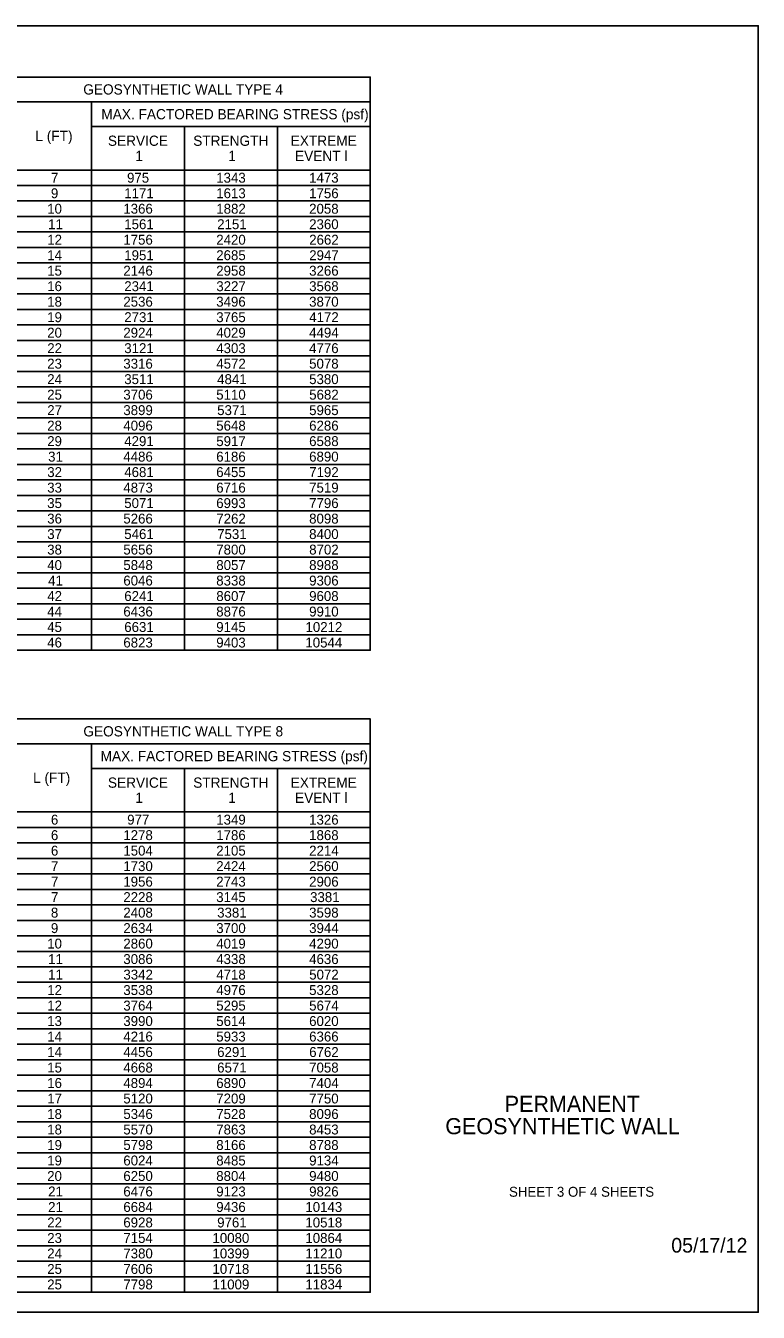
# Model space of a CAD drawing. Extents: x 99862 to 103151, y 100000 to 111076.
# Drawn here: x 101968 to 103151, y 106000 to 108076 of the extents above; entities that cross this region are included whole.
import ezdxf

# ---------------------------------------------------------------- set-up
doc = ezdxf.new("R2010")
doc.units = 0
for name, color, linetype in [('Level 1', 7, 'Continuous'), ('Level 20', 7, 'Continuous'), ('Level 40', 7, 'Continuous'), ('Level 60', 7, 'Continuous'), ('Level 62', 7, 'Continuous')]:
    doc.layers.add(name, color=color, linetype=linetype)

msp = doc.modelspace()

# ---------------------------------------------------------------- linework, layer by layer
at = {"layer": 'Level 1'}
msp.add_lwpolyline([(99862, 105999.5), (103151, 105999.5), (103151, 108075.5), (99862, 108075.5)], close=True, dxfattribs=at)
at = {"layer": 'Level 40'}
for p, q in [((100094.6, 107952.7), (102524.6, 107952.7)), ((102074.6, 107952.7), (102074.6, 107067.7)), ((102074.6, 107912.7), (102524.6, 107912.7)), ((102224.6, 107912.7), (102224.6, 107067.7)), ((102374.6, 107912.7), (102374.6, 107067.7)), ((99944.6, 107842.7), (102524.6, 107842.7)), ((99944.6, 107817.7), (102524.6, 107817.7)), ((99944.6, 107792.7), (102524.6, 107792.7)), ((99944.6, 107767.7), (102524.6, 107767.7)), ((99944.6, 107742.7), (102524.6, 107742.7)), ((99944.6, 107717.7), (102524.6, 107717.7)), ((99944.6, 107692.7), (102524.6, 107692.7)), ((99944.6, 107667.7), (102524.6, 107667.7)), ((99944.6, 107642.7), (102524.6, 107642.7)), ((99944.6, 107617.7), (102524.6, 107617.7)), ((99944.6, 107592.7), (102524.6, 107592.7)), ((99944.6, 107567.7), (102524.6, 107567.7)), ((99944.6, 107542.7), (102524.6, 107542.7)), ((99944.6, 107517.7), (102524.6, 107517.7)), ((99944.6, 107492.7), (102524.6, 107492.7)), ((99944.6, 107467.7), (102524.6, 107467.7)), ((99944.6, 107442.7), (102524.6, 107442.7)), ((99944.6, 107417.7), (102524.6, 107417.7)), ((99944.6, 107392.7), (102524.6, 107392.7)), ((99944.6, 107367.7), (102524.6, 107367.7)), ((99944.6, 107342.7), (102524.6, 107342.7)), ((99944.6, 107317.7), (102524.6, 107317.7)), ((99944.6, 107292.7), (102524.6, 107292.7)), ((99944.6, 107267.7), (102524.6, 107267.7)), ((99944.6, 107242.7), (102524.6, 107242.7)), ((99944.6, 107217.7), (102524.6, 107217.7)), ((99944.6, 107192.7), (102524.6, 107192.7)), ((99944.6, 107167.7), (102524.6, 107167.7)), ((99944.6, 107142.7), (102524.6, 107142.7)), ((99944.6, 107117.7), (102524.6, 107117.7)), ((99944.6, 107092.7), (102524.6, 107092.7)), ((100094.6, 106916.9), (102524.6, 106916.9)), ((102074.6, 106916.9), (102074.6, 106031.9)), ((102074.6, 106876.9), (102524.6, 106876.9)), ((102224.6, 106876.9), (102224.6, 106031.9)), ((102374.6, 106876.9), (102374.6, 106031.9)), ((99944.6, 106806.9), (102524.6, 106806.9)), ((99944.6, 106781.9), (102524.6, 106781.9)), ((99944.6, 106756.9), (102524.6, 106756.9)), ((99944.6, 106731.9), (102524.6, 106731.9)), ((99944.6, 106706.9), (102524.6, 106706.9)), ((99944.6, 106681.9), (102524.6, 106681.9)), ((99944.6, 106656.9), (102524.6, 106656.9)), ((99944.6, 106631.9), (102524.6, 106631.9)), ((99944.6, 106606.9), (102524.6, 106606.9)), ((99944.6, 106581.9), (102524.6, 106581.9)), ((99944.6, 106556.9), (102524.6, 106556.9)), ((99944.6, 106531.9), (102524.6, 106531.9)), ((99944.6, 106506.9), (102524.6, 106506.9)), ((99944.6, 106481.9), (102524.6, 106481.9)), ((99944.6, 106456.9), (102524.6, 106456.9)), ((99944.6, 106431.9), (102524.6, 106431.9)), ((99944.6, 106406.9), (102524.6, 106406.9)), ((99944.6, 106381.9), (102524.6, 106381.9)), ((99944.6, 106356.9), (102524.6, 106356.9)), ((99944.6, 106331.9), (102524.6, 106331.9)), ((99944.6, 106306.9), (102524.6, 106306.9)), ((99944.6, 106281.9), (102524.6, 106281.9)), ((99944.6, 106256.9), (102524.6, 106256.9)), ((99944.6, 106231.9), (102524.6, 106231.9)), ((99944.6, 106206.9), (102524.6, 106206.9)), ((99944.6, 106181.9), (102524.6, 106181.9)), ((99944.6, 106156.9), (102524.6, 106156.9)), ((99944.6, 106131.9), (102524.6, 106131.9)), ((99944.6, 106106.9), (102524.6, 106106.9)), ((99944.6, 106081.9), (102524.6, 106081.9)), ((99944.6, 106056.9), (102524.6, 106056.9))]:
    msp.add_line(p, q, dxfattribs=at)
for points in [[(99944.6, 107992.7), (102524.6, 107992.7), (102524.6, 107067.7), (99944.6, 107067.7)], [(99944.6, 106956.9), (102524.6, 106956.9), (102524.6, 106031.9), (99944.6, 106031.9)]]:
    msp.add_lwpolyline(points, close=True, dxfattribs=at)
at = {"layer": 'Level 60'}
msp.add_line((103151, 108075.5), (103151, 108075.5), dxfattribs=at)

# ---------------------------------------------------------------- texts
at = {"layer": 'Level 1'}
msp.add_text('05/17/12', height=23.62, dxfattribs=at).set_placement((103010.5, 106095.8))
at = {"layer": 'Level 20'}
for s, height, p in [('GEOSYNTHETIC WALL TYPE 4', 16.5, (102061.2, 107964.5)), ('MAX. FACTORED BEARING STRESS (psf)', 16.5, (102090.4, 107924.5)), ('L (FT)', 16.5, (101983.9, 107889.5)), ('SERVICE', 16.5, (102101, 107881.7)), ('STRENGTH', 16.5, (102238.7, 107881.7)), ('EXTREME', 16.5, (102396.1, 107881.7)), ('1', 16.5, (102145.2, 107857.2)), ('1', 16.5, (102295.2, 107857.2)), ('EVENT l', 16.5, (102403.1, 107857.2)), ('7', 16, (102009.2, 107822.2)), ('975', 16, (102131.9, 107822.2)), ('1343', 16, (102275.9, 107822.2)), ('1473', 16, (102425.9, 107822.2)), ('9', 16, (102009, 107797.2)), ('1171', 16, (102127.4, 107797.2)), ('1613', 16, (102275.9, 107797.2)), ('1756', 16, (102425.9, 107797.2)), ('10', 16, (102003, 107772.2)), ('1366', 16, (102125.9, 107772.2)), ('1882', 16, (102276, 107772.2)), ('2058', 16, (102425.9, 107772.2)), ('11', 16, (102004.5, 107747.2)), ('1561', 16, (102127.4, 107747.2)), ('2151', 16, (102277.4, 107747.2)), ('2360', 16, (102425.9, 107747.2)), ('12', 16, (102003.1, 107722.2)), ('1756', 16, (102125.9, 107722.2)), ('2420', 16, (102275.9, 107722.2)), ('2662', 16, (102426, 107722.2)), ('14', 16, (102003, 107697.2)), ('1951', 16, (102127.4, 107697.2)), ('2685', 16, (102275.9, 107697.2)), ('2947', 16, (102426, 107697.2)), ('15', 16, (102003, 107672.2)), ('2146', 16, (102125.9, 107672.2)), ('2958', 16, (102275.9, 107672.2)), ('3266', 16, (102425.9, 107672.2)), ('16', 16, (102003, 107647.2)), ('2341', 16, (102127.4, 107647.2)), ('3227', 16, (102276, 107647.2)), ('3568', 16, (102425.9, 107647.2)), ('18', 16, (102003, 107622.2)), ('2536', 16, (102125.9, 107622.2)), ('3496', 16, (102275.9, 107622.2)), ('3870', 16, (102425.9, 107622.2)), ('19', 16, (102003, 107597.2)), ('2731', 16, (102127.4, 107597.2)), ('3765', 16, (102275.9, 107597.2)), ('4172', 16, (102426, 107597.2)), ('20', 16, (102003, 107572.2)), ('2924', 16, (102125.9, 107572.2)), ('4029', 16, (102275.9, 107572.2)), ('4494', 16, (102425.9, 107572.2)), ('22', 16, (102003.1, 107547.2)), ('3121', 16, (102127.4, 107547.2)), ('4303', 16, (102275.9, 107547.2)), ('4776', 16, (102425.9, 107547.2)), ('23', 16, (102003, 107522.2)), ('3316', 16, (102125.9, 107522.2)), ('4572', 16, (102276, 107522.2)), ('5078', 16, (102425.9, 107522.2)), ('24', 16, (102003, 107497.2)), ('3511', 16, (102127.4, 107497.2)), ('4841', 16, (102277.4, 107497.2)), ('5380', 16, (102425.9, 107497.2)), ('25', 16, (102003, 107472.2)), ('3706', 16, (102125.9, 107472.2)), ('5110', 16, (102275.9, 107472.2)), ('5682', 16, (102426, 107472.2)), ('27', 16, (102003.1, 107447.2)), ('3899', 16, (102125.9, 107447.2)), ('5371', 16, (102277.4, 107447.2)), ('5965', 16, (102425.9, 107447.2)), ('28', 16, (102003, 107422.2)), ('4096', 16, (102125.9, 107422.2)), ('5648', 16, (102275.9, 107422.2)), ('6286', 16, (102425.9, 107422.2)), ('29', 16, (102003, 107397.2)), ('4291', 16, (102127.4, 107397.2)), ('5917', 16, (102276, 107397.2)), ('6588', 16, (102425.9, 107397.2)), ('31', 16, (102004.5, 107372.2)), ('4486', 16, (102125.9, 107372.2)), ('6186', 16, (102275.9, 107372.2)), ('6890', 16, (102425.9, 107372.2)), ('32', 16, (102003.1, 107347.2)), ('4681', 16, (102127.4, 107347.2)), ('6455', 16, (102275.9, 107347.2)), ('7192', 16, (102426, 107347.2)), ('33', 16, (102003, 107322.2)), ('4873', 16, (102125.9, 107322.2)), ('6716', 16, (102275.9, 107322.2)), ('7519', 16, (102425.9, 107322.2)), ('35', 16, (102003, 107297.2)), ('5071', 16, (102127.4, 107297.2)), ('6993', 16, (102275.9, 107297.2)), ('7796', 16, (102425.9, 107297.2)), ('36', 16, (102003, 107272.2)), ('5266', 16, (102125.9, 107272.2)), ('7262', 16, (102276, 107272.2)), ('8098', 16, (102425.9, 107272.2)), ('37', 16, (102003.1, 107247.2)), ('5461', 16, (102127.4, 107247.2)), ('7531', 16, (102277.4, 107247.2)), ('8400', 16, (102425.9, 107247.2)), ('38', 16, (102003, 107222.2)), ('5656', 16, (102125.9, 107222.2)), ('7800', 16, (102275.9, 107222.2)), ('8702', 16, (102426, 107222.2)), ('40', 16, (102003, 107197.2)), ('5848', 16, (102125.9, 107197.2)), ('8057', 16, (102276, 107197.2)), ('8988', 16, (102425.9, 107197.2)), ('41', 16, (102004.5, 107172.2)), ('6046', 16, (102125.9, 107172.2)), ('8338', 16, (102275.9, 107172.2)), ('9306', 16, (102425.9, 107172.2)), ('42', 16, (102003.1, 107147.2)), ('6241', 16, (102127.4, 107147.2)), ('8607', 16, (102276, 107147.2)), ('9608', 16, (102425.9, 107147.2)), ('44', 16, (102003, 107122.2)), ('6436', 16, (102125.9, 107122.2)), ('8876', 16, (102275.9, 107122.2)), ('9910', 16, (102425.9, 107122.2)), ('45', 16, (102003, 107097.2)), ('6631', 16, (102127.4, 107097.2)), ('9145', 16, (102275.9, 107097.2)), ('10212', 16, (102420, 107097.2)), ('46', 16, (102003, 107072.2)), ('6823', 16, (102125.9, 107072.2)), ('9403', 16, (102275.9, 107072.2)), ('10544', 16, (102419.8, 107072.2)), ('GEOSYNTHETIC WALL TYPE 8', 16.5, (102061.4, 106928.7)), ('MAX. FACTORED BEARING STRESS (psf)', 16.5, (102089.2, 106888.7)), ('L (FT)', 16.5, (101980.2, 106853.7)), ('SERVICE', 16.5, (102101, 106845.9)), ('STRENGTH', 16.5, (102238.7, 106845.9)), ('EXTREME', 16.5, (102396.1, 106845.9)), ('1', 16.5, (102145.2, 106821.4)), ('1', 16.5, (102295.2, 106821.4)), ('EVENT l', 16.5, (102403.1, 106821.4)), ('6', 16, (102009, 106786.4)), ('977', 16, (102132.1, 106786.4)), ('1349', 16, (102275.9, 106786.4)), ('1326', 16, (102425.9, 106786.4)), ('6', 16, (102009, 106761.4)), ('1278', 16, (102125.9, 106761.4)), ('1786', 16, (102275.9, 106761.4)), ('1868', 16, (102425.9, 106761.4)), ('6', 16, (102009, 106736.4)), ('1504', 16, (102125.9, 106736.4)), ('2105', 16, (102275.9, 106736.4)), ('2214', 16, (102425.9, 106736.4)), ('7', 16, (102009.2, 106711.4)), ('1730', 16, (102125.9, 106711.4)), ('2424', 16, (102275.9, 106711.4)), ('2560', 16, (102425.9, 106711.4)), ('7', 16, (102009.2, 106686.4)), ('1956', 16, (102125.9, 106686.4)), ('2743', 16, (102275.9, 106686.4)), ('2906', 16, (102425.9, 106686.4)), ('7', 16, (102009.2, 106661.4)), ('2228', 16, (102125.9, 106661.4)), ('3145', 16, (102275.9, 106661.4)), ('3381', 16, (102427.4, 106661.4)), ('8', 16, (102009, 106636.4)), ('2408', 16, (102125.9, 106636.4)), ('3381', 16, (102277.4, 106636.4)), ('3598', 16, (102425.9, 106636.4)), ('9', 16, (102009, 106611.4)), ('2634', 16, (102125.9, 106611.4)), ('3700', 16, (102275.9, 106611.4)), ('3944', 16, (102425.9, 106611.4)), ('10', 16, (102003, 106586.4)), ('2860', 16, (102125.9, 106586.4)), ('4019', 16, (102275.9, 106586.4)), ('4290', 16, (102425.9, 106586.4)), ('11', 16, (102004.5, 106561.4)), ('3086', 16, (102125.9, 106561.4)), ('4338', 16, (102275.9, 106561.4)), ('4636', 16, (102425.9, 106561.4)), ('11', 16, (102004.5, 106536.4)), ('3342', 16, (102126, 106536.4)), ('4718', 16, (102275.9, 106536.4)), ('5072', 16, (102426, 106536.4)), ('12', 16, (102003.1, 106511.4)), ('3538', 16, (102125.9, 106511.4)), ('4976', 16, (102275.9, 106511.4)), ('5328', 16, (102425.9, 106511.4)), ('12', 16, (102003.1, 106486.4)), ('3764', 16, (102125.9, 106486.4)), ('5295', 16, (102275.9, 106486.4)), ('5674', 16, (102425.9, 106486.4)), ('13', 16, (102003, 106461.4)), ('3990', 16, (102125.9, 106461.4)), ('5614', 16, (102275.9, 106461.4)), ('6020', 16, (102425.9, 106461.4)), ('14', 16, (102003, 106436.4)), ('4216', 16, (102125.9, 106436.4)), ('5933', 16, (102275.9, 106436.4)), ('6366', 16, (102425.9, 106436.4)), ('14', 16, (102003, 106411.4)), ('4456', 16, (102125.9, 106411.4)), ('6291', 16, (102277.4, 106411.4)), ('6762', 16, (102426, 106411.4)), ('15', 16, (102003, 106386.4)), ('4668', 16, (102125.9, 106386.4)), ('6571', 16, (102277.4, 106386.4)), ('7058', 16, (102425.9, 106386.4)), ('16', 16, (102003, 106361.4)), ('4894', 16, (102125.9, 106361.4)), ('6890', 16, (102275.9, 106361.4)), ('7404', 16, (102425.9, 106361.4)), ('17', 16, (102003.1, 106336.4)), ('5120', 16, (102125.9, 106336.4)), ('7209', 16, (102275.9, 106336.4)), ('7750', 16, (102425.9, 106336.4)), ('18', 16, (102003, 106311.4)), ('5346', 16, (102125.9, 106311.4)), ('7528', 16, (102275.9, 106311.4)), ('8096', 16, (102425.9, 106311.4)), ('18', 16, (102003, 106286.4)), ('5570', 16, (102125.9, 106286.4)), ('7863', 16, (102275.9, 106286.4)), ('8453', 16, (102425.9, 106286.4)), ('19', 16, (102003, 106261.4)), ('5798', 16, (102125.9, 106261.4)), ('8166', 16, (102275.9, 106261.4)), ('8788', 16, (102425.9, 106261.4)), ('19', 16, (102003, 106236.4)), ('6024', 16, (102125.9, 106236.4)), ('8485', 16, (102275.9, 106236.4)), ('9134', 16, (102425.9, 106236.4)), ('20', 16, (102003, 106211.4)), ('6250', 16, (102125.9, 106211.4)), ('8804', 16, (102275.9, 106211.4)), ('9480', 16, (102425.9, 106211.4)), ('21', 16, (102004.5, 106186.4)), ('6476', 16, (102125.9, 106186.4)), ('9123', 16, (102275.9, 106186.4)), ('9826', 16, (102425.9, 106186.4)), ('21', 16, (102004.5, 106161.4)), ('6684', 16, (102125.9, 106161.4)), ('9436', 16, (102275.9, 106161.4)), ('10143', 16, (102419.8, 106161.4)), ('22', 16, (102003.1, 106136.4)), ('6928', 16, (102125.9, 106136.4)), ('9761', 16, (102277.4, 106136.4)), ('10518', 16, (102419.8, 106136.4)), ('23', 16, (102003, 106111.4)), ('7154', 16, (102125.9, 106111.4)), ('10080', 16, (102269.8, 106111.4)), ('10864', 16, (102419.8, 106111.4)), ('24', 16, (102003, 106086.4)), ('7380', 16, (102125.9, 106086.4)), ('10399', 16, (102269.8, 106086.4)), ('11210', 16, (102419.8, 106086.4)), ('25', 16, (102003, 106061.4)), ('7606', 16, (102125.9, 106061.4)), ('10718', 16, (102269.8, 106061.4)), ('11556', 16, (102419.8, 106061.4)), ('25', 16, (102003, 106036.4)), ('7798', 16, (102125.9, 106036.4)), ('11009', 16, (102269.8, 106036.4)), ('11834', 16, (102419.8, 106036.4))]:
    msp.add_text(s, height=height, dxfattribs=at).set_placement(p)
at = {"layer": 'Level 62'}
for s, height, p in [('PERMANENT', 26, (102741.6, 106322.8)), ('GEOSYNTHETIC WALL', 26, (102645.7, 106286.8)), ('SHEET 3 OF 4 SHEETS', 16, (102748.6, 106185.9))]:
    msp.add_text(s, height=height, dxfattribs=at).set_placement(p)

doc.saveas('drawing.dxf')
